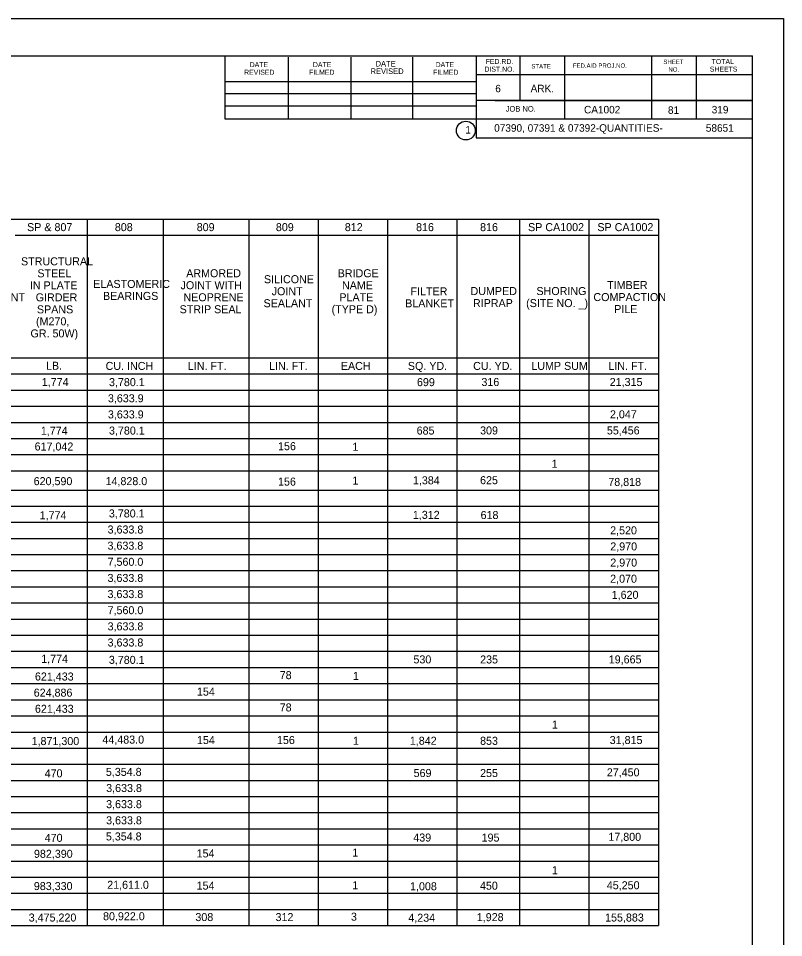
# Model space of a CAD drawing. Extents: x 117751.5 to 117785.6, y 28052.1 to 28074.
# Drawn here: x 117773.71 to 117785.65, y 28059.6 to 28073.96 of the extents above; entities that cross this region are included whole.
import ezdxf

# ---------------------------------------------------------------- set-up
doc = ezdxf.new("R2010")
doc.units = 0
for name, color, linetype in [('border', 7, 'Continuous'), ('Level 1', 7, 'Continuous'), ('Level 40', 7, 'Continuous'), ('Level 62', 7, 'Continuous'), ('Text', 7, 'Continuous')]:
    doc.layers.add(name, color=color, linetype=linetype)

msp = doc.modelspace()

# ---------------------------------------------------------------- linework, layer by layer
at = {"layer": 'border'}
for p, q in [((117753.15, 28073.371), (117785.161, 28073.371)), ((117776.935, 28072.383), (117776.935, 28073.371)), ((117777.92, 28072.383), (117777.92, 28073.352)), ((117778.897, 28072.383), (117778.897, 28073.352)), ((117779.864, 28072.383), (117779.864, 28073.352)), ((117780.85, 28073.371), (117780.85, 28072.092)), ((117781.534, 28073.371), (117781.534, 28072.677)), ((117782.229, 28073.371), (117782.229, 28072.383)), ((117783.586, 28073.371), (117783.586, 28072.383)), ((117784.281, 28073.371), (117784.281, 28072.383)), ((117785.161, 28052.826), (117785.161, 28073.371)), ((117785.161, 28073.077), (117780.85, 28073.077)), ((117785.161, 28073.079), (117785.161, 28073.079)), ((117776.935, 28072.969), (117780.85, 28072.969)), ((117776.935, 28072.783), (117780.85, 28072.783)), ((117785.161, 28072.677), (117780.85, 28072.677)), ((117781.147, 28072.677), (117785.161, 28072.677)), ((117776.935, 28072.383), (117776.935, 28072.59)), ((117776.935, 28072.59), (117780.85, 28072.59)), ((117785.161, 28072.383), (117776.935, 28072.383)), ((117780.85, 28072.092), (117785.161, 28072.092))]:
    msp.add_line(p, q, dxfattribs=at)
msp.add_circle((117780.689, 28072.205), 0.147, dxfattribs=at)
at = {"layer": 'Level 1'}
for p, q in [((117754.881, 28070.823), (117783.697, 28070.823)), ((117774.785, 28059.793), (117774.785, 28070.823)), ((117775.971, 28059.793), (117775.971, 28070.823)), ((117777.308, 28059.793), (117777.308, 28070.823)), ((117778.39, 28059.793), (117778.39, 28070.823)), ((117779.472, 28059.793), (117779.472, 28070.823)), ((117780.554, 28059.793), (117780.554, 28070.823)), ((117781.532, 28059.793), (117781.532, 28070.823)), ((117782.614, 28059.793), (117782.614, 28070.823)), ((117783.697, 28070.823), (117783.697, 28059.793)), ((117773.657, 28070.571), (117775.971, 28070.571)), ((117775.971, 28070.571), (117783.697, 28070.571)), ((117759.038, 28068.657), (117783.697, 28068.657)), ((117754.881, 28068.405), (117783.697, 28068.405)), ((117755.637, 28068.153), (117783.697, 28068.153)), ((117755.637, 28067.901), (117783.697, 28067.901)), ((117755.637, 28067.65), (117783.697, 28067.649)), ((117755.637, 28067.398), (117783.697, 28067.398)), ((117755.637, 28067.146), (117783.697, 28067.146)), ((117754.881, 28066.894), (117783.697, 28066.894)), ((117754.881, 28066.593), (117783.697, 28066.593)), ((117754.881, 28066.342), (117783.697, 28066.342)), ((117755.637, 28066.09), (117783.697, 28066.09)), ((117755.637, 28065.838), (117783.697, 28065.838)), ((117755.637, 28065.586), (117783.697, 28065.586)), ((117755.637, 28065.334), (117783.697, 28065.334)), ((117755.637, 28065.082), (117783.697, 28065.082)), ((117755.637, 28064.83), (117783.697, 28064.83)), ((117755.637, 28064.578), (117783.697, 28064.578)), ((117755.637, 28064.327), (117783.697, 28064.327)), ((117755.637, 28064.075), (117783.697, 28064.075)), ((117755.637, 28063.823), (117783.697, 28063.823)), ((117755.637, 28063.571), (117783.697, 28063.571)), ((117755.637, 28063.319), (117783.697, 28063.319)), ((117755.637, 28063.067), (117783.697, 28063.067)), ((117754.881, 28062.815), (117783.697, 28062.815)), ((117754.881, 28062.563), (117783.697, 28062.563)), ((117754.881, 28062.312), (117783.697, 28062.312)), ((117755.637, 28062.06), (117783.697, 28062.06)), ((117755.637, 28061.808), (117783.697, 28061.808)), ((117755.637, 28061.556), (117783.697, 28061.556)), ((117755.637, 28061.304), (117783.697, 28061.304)), ((117755.637, 28061.052), (117783.697, 28061.052)), ((117755.637, 28060.8), (117783.697, 28060.8)), ((117754.881, 28060.548), (117783.697, 28060.548)), ((117754.881, 28060.297), (117783.697, 28060.297)), ((117754.881, 28060.045), (117783.697, 28060.045)), ((117754.881, 28059.793), (117783.697, 28059.793))]:
    msp.add_line(p, q, dxfattribs=at)
at = {"layer": 'Level 62'}
msp.add_lwpolyline([(117751.53, 28073.957), (117785.648, 28073.957), (117785.648, 28052.147), (117751.53, 28052.147)], close=True, dxfattribs=at)

# ---------------------------------------------------------------- texts
at = {"layer": 'Level 1'}
for s, height, p in [('81', 0.1172, (117783.843, 28072.466)), ('07390, 07391 & 07392-QUANTITIES-', 0.11722, (117781.131, 28072.187)), ('58651', 0.1172, (117784.434, 28072.187))]:
    msp.add_text(s, height=height, dxfattribs=at).set_placement(p)
at = {"layer": 'Level 40'}
for s, p in [('SP & 807', (117773.842, 28070.635)), ('808', (117775.211, 28070.635)), ('809', (117776.489, 28070.635)), ('809', (117777.724, 28070.635)), ('812', (117778.8, 28070.635)), ('816', (117779.912, 28070.635)), ('816', (117780.911, 28070.635)), ('SP CA1002', (117781.66, 28070.635)), ('SP CA1002', (117782.742, 28070.635)), ('STRUCTURAL', (117773.747, 28070.101)), ('STEEL', (117774.002, 28069.914)), ('ARMORED', (117776.325, 28069.915)), ('BRIDGE', (117778.689, 28069.915)), ('ELASTOMERIC', (117774.874, 28069.748)), ('SILICONE', (117777.538, 28069.822)), ('IN PLATE', (117773.885, 28069.726)), ('JOINT WITH', (117776.237, 28069.728)), ('JOINT', (117777.659, 28069.634)), ('NAME', (117778.756, 28069.728)), ('FILTER', (117779.825, 28069.633)), ('DUMPED', (117780.762, 28069.637)), ('SHORING', (117781.791, 28069.637)), ('TIMBER', (117782.894, 28069.731)), ('ENCASEMENT', (117772.648, 28069.54)), ('GIRDER', (117773.976, 28069.539)), ('BEARINGS', (117775.026, 28069.561)), ('NEOPRENE', (117776.282, 28069.54)), ('PLATE', (117778.715, 28069.54)), ('(SITE NO. _)', (117781.63, 28069.449)), ('COMPACTION', (117782.68, 28069.543)), ('SPANS', (117773.995, 28069.351)), ('STRIP SEAL', (117776.222, 28069.353)), ('SEALANT', (117777.532, 28069.447)), ('(TYPE D)', (117778.594, 28069.353)), ('BLANKET', (117779.742, 28069.445)), ('RIPRAP', (117780.8, 28069.449)), ('PILE', (117783.004, 28069.356)), ('(M270,', (117773.981, 28069.164)), ('GR. 50W)', (117773.895, 28068.976)), ('LB.', (117774.137, 28068.471)), ('CU. INCH', (117775.067, 28068.468)), ('LIN. FT.', (117776.351, 28068.468)), ('LIN. FT.', (117777.618, 28068.468)), ('EACH', (117778.738, 28068.468)), ('SQ. YD.', (117779.784, 28068.468)), ('CU. YD.', (117780.803, 28068.468)), ('LUMP SUM', (117781.711, 28068.468)), ('LIN. FT.', (117782.913, 28068.468)), ('1,774', (117774.071, 28068.217)), ('3,780.1', (117775.12, 28068.215)), ('699', (117779.926, 28068.215)), ('316', (117780.932, 28068.217)), ('21,315', (117782.934, 28068.217)), ('3,633.9', (117775.103, 28067.963)), ('3,633.9', (117775.103, 28067.711)), ('2,047', (117782.938, 28067.713)), ('1,774', (117774.056, 28067.456)), ('3,780.1', (117775.12, 28067.459)), ('685', (117779.921, 28067.459)), ('309', (117780.911, 28067.461)), ('55,456', (117782.89, 28067.461)), ('617,042', (117773.959, 28067.21)), ('156', (117777.758, 28067.215)), ('1', (117778.919, 28067.206)), ('1', (117782.028, 28066.941)), ('620,590', (117773.944, 28066.669)), ('14,828.0', (117775.066, 28066.669)), ('156', (117777.758, 28066.662)), ('1', (117778.919, 28066.679)), ('1,384', (117779.863, 28066.682)), ('625', (117780.911, 28066.684)), ('78,818', (117782.912, 28066.657)), ('3,780.1', (117775.118, 28066.165)), ('1,774', (117774.038, 28066.137)), ('1,312', (117779.862, 28066.143)), ('618', (117780.919, 28066.14)), ('3,633.8', (117775.098, 28065.914)), ('2,520', (117782.941, 28065.901)), ('3,633.8', (117775.097, 28065.662)), ('2,970', (117782.943, 28065.65)), ('7,560.0', (117775.098, 28065.41)), ('2,970', (117782.943, 28065.398)), ('3,633.8', (117775.097, 28065.158)), ('2,070', (117782.941, 28065.146)), ('3,633.8', (117775.097, 28064.906)), ('1,620', (117782.965, 28064.894)), ('7,560.0', (117775.098, 28064.654)), ('3,633.8', (117775.098, 28064.402)), ('3,633.8', (117775.098, 28064.15)), ('1,774', (117774.062, 28063.895)), ('3,780.1', (117775.118, 28063.879)), ('530', (117779.871, 28063.886)), ('235', (117780.912, 28063.885)), ('19,665', (117782.919, 28063.886)), ('621,433', (117773.964, 28063.619)), ('78', (117777.784, 28063.64)), ('1', (117778.928, 28063.629)), ('624,886', (117773.945, 28063.367)), ('154', (117776.493, 28063.383)), ('621,433', (117773.964, 28063.115)), ('78', (117777.784, 28063.136)), ('1', (117782.032, 28062.867)), ('1,871,300', (117773.912, 28062.611)), ('44,483.0', (117775.017, 28062.634)), ('154', (117776.493, 28062.627)), ('156', (117777.741, 28062.627)), ('1', (117778.928, 28062.616)), ('1,842', (117779.815, 28062.616)), ('853', (117780.911, 28062.615)), ('31,815', (117782.934, 28062.627)), ('470', (117774.116, 28062.107)), ('5,354.8', (117775.071, 28062.13)), ('569', (117779.874, 28062.112)), ('255', (117780.911, 28062.112)), ('27,450', (117782.889, 28062.123)), ('3,633.8', (117775.076, 28061.878)), ('3,633.8', (117775.075, 28061.626)), ('3,633.8', (117775.075, 28061.374)), ('470', (117774.116, 28061.1)), ('5,354.8', (117775.071, 28061.122)), ('439', (117779.869, 28061.105)), ('195', (117780.935, 28061.104)), ('17,800', (117782.913, 28061.116)), ('982,390', (117773.949, 28060.851)), ('154', (117776.487, 28060.857)), ('1', (117778.917, 28060.87)), ('1', (117782.032, 28060.595)), ('983,330', (117773.947, 28060.347)), ('21,611.0', (117775.092, 28060.367)), ('154', (117776.487, 28060.354)), ('1', (117778.917, 28060.36)), ('1,008', (117779.818, 28060.344)), ('450', (117780.909, 28060.353)), ('45,250', (117782.889, 28060.36)), ('3,475,220', (117773.867, 28059.856)), ('80,922.0', (117775.027, 28059.876)), ('308', (117776.468, 28059.863)), ('312', (117777.719, 28059.863)), ('3', (117778.896, 28059.869)), ('4,234', (117779.791, 28059.853)), ('1,928', (117780.86, 28059.862)), ('155,883', (117782.862, 28059.856))]:
    msp.add_text(s, height=0.125, dxfattribs=at).set_placement(p)
at = {"layer": 'Text'}
for s, height, p in [('FED.RD.', 0.0782, (117780.998, 28073.244)), ('SHEET', 0.0684, (117783.772, 28073.244)), ('TOTAL', 0.0782, (117784.525, 28073.244)), ('DATE', 0.0782, (117777.315, 28073.196)), ('DATE', 0.0782, (117778.302, 28073.196)), ('REVISED', 0.0879, (117779.202, 28073.088)), ('DATE', 0.0879, (117779.28, 28073.205)), ('DATE', 0.0782, (117780.217, 28073.196)), ('DIST.NO.', 0.0782, (117780.979, 28073.125)), ('STATE', 0.0684, (117781.711, 28073.175)), ('FED.AID PROJ.NO.', 0.06839, (117782.358, 28073.185)), ('NO.', 0.0684, (117783.85, 28073.125)), ('SHEETS', 0.0782, (117784.496, 28073.125)), ('REVISED', 0.0782, (117777.228, 28073.077)), ('FILMED', 0.0782, (117778.243, 28073.077)), ('FILMED', 0.0782, (117780.177, 28073.077)), ('6', 0.117, (117781.148, 28072.803)), ('ARK.', 0.1172, (117781.7, 28072.803)), ('JOB NO.', 0.0879, (117781.311, 28072.501)), ('CA1002', 0.1172, (117782.533, 28072.473)), ('319', 0.1172, (117784.526, 28072.473)), ('1', 0.117, (117780.682, 28072.158))]:
    msp.add_text(s, height=height, dxfattribs=at).set_placement(p)

doc.saveas('drawing.dxf')
